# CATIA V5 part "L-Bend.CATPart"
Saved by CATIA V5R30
Part number: L-Bend
Bounding box of the stored display mesh (mm): x -50 to 50, y -130 to 15, z -50 to 100
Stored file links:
  D:\PROJECTS\CATIA V56R 2020\Resources\Parts File\c12_catia_v5_6r2020_prt\c12_catia_v5-6r2020 figr_12-39\L-Bend.CATPart
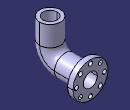
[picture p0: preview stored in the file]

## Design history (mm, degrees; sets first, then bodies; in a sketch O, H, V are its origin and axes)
Body1 (main body)
  Sketch1 on yz-plane, origin (0, 0, 0), H (0, 1, 0), V (0, 0, 1)
    line L1 (0, 0) -> (-57.4642, 0)
    point P1 (-100, 0)
    line L2 (-100, 42.5358) -> (-100, 100)
    point P2 (-100, 100)
    arc A1 centre (-57.4642, 42.5358) radius 42.5358 from (-100, 42.5358) to (-57.4642, 0) ccw
    distance P1 P2 = 100
    distance O P1 = 100
    radius A1 = 42.5358
    horizontal: L1 H
    vertical: L2 V
    coincidence: L2 P1, L1 P1
    tangency: A1 L2, A1 L1
  Sketch2 on zx-plane, origin (0, 0, 0), H (-1, 0, 0), V (0, 0, 1)
    circle A1 centre (0, 0) radius 30
    point P1 (0, -30)
    radius A1 = 30
    coincidence: A1 P1, P1 V
  Rib1: profile Sketch2, centre curve Sketch1
  Shell1: ExtOffset 0, Face (face of Rib1; face of Rib1), IntOffset 10
  Sketch3 on face of Rib1, origin (0, 0, 0), H (-1, 0, 0), V (0, 0, 1)
    circle A1 centre (0, 0) radius 50
    point P1 (0, -50)
    projected circle E1 centre (0, 0) radius 20 from edge [face of Shell1 | face of Rib1]
    radius A1 = 50
    coincidence: A1 P1, P1 V
  Pad1: profile Sketch3, direction (0, 1, 0), length 15
  Sketch4 on face of Pad1, origin (0, 15, 0), H (-1, 0, 0), V (0, 0, 1)
    circle A1 centre (0, -40) radius 6
    point P1 (0, -40)
    radius A1 = 6
    distance H P1 = 40
    coincidence: P1 V
  Pocket1: profile Sketch4, direction (0, -1, 0), length 15
  CircPattern1: of Pocket1, instances 8, angular step 45, axis from face of Pad1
